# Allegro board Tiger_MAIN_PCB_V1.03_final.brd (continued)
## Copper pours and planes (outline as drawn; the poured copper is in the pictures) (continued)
+V3P3A_DSW on TOP (solid shape): 143.64,93.38 143.64,88.98 143.41,88.76 142.41,88.76 142.17,89 142.17,93.23 142.4,93.45 143.57,93.45
+V3P3A_DSW on TOP (solid shape): outline of 113 points within 7.45,60.28 19.2,69.48
+V3P3A_DSW on BOTTOM (solid shape): 37.52,56.22 37.52,53.65 37.32,53.46 36.44,53.46 35.46,54.44 35.46,55.96 35.85,56.36 37.38,56.36
+V3P3A_DSW on LAY6 (solid shape): outline of 455 points within 9.48,48.32 37.95,63.17
+V3P3A_RTC on BOTTOM (solid shape): 197.68,61.61 197.76,61.53 197.82,61.53 197.93,61.42 197.93,61.19 197.91,61.15 197.88,61.14 197.55,60.92 197.62,60.53 197.64,60.49 197.64,60.44 197.64,59.85 197.64,59.8 197.62,59.76 197.52,59.51 197.65,59.2 197.52,58.88 197.65,58.56 197.62,58.49 197.52,58.18 197.72,57.92 197.74,57.91 197.77,57.87 197.77,55.43 196.97,54.63 196.73,54.63 195.99,53.9 195.99,53.65 195.05,52.71 194.49,52.71 194.28,52.5 194.28,51.52 193.74,50.99 193.74,49.84 193.46,49.56 193.19,49.56 192.97,49.78 192.97,53.14 194.42,54.58 195.64,54.58 197.09,56.04 197.09,56.06 197.12,56.11 197.13,56.11 197.29,56.41 197.13,56.7 197.12,56.71 197.09,56.75 197.09,57.26 197.13,57.29 197.31,57.55 197.22,57.86 197.19,57.93 197.32,58.24 197.19,58.56 197.32,58.88 197.19,59.2 197.32,59.51 197.19,59.83 197.32,60.15 197.19,60.47 197.32,60.78 197.19,61.1 197.22,61.17 197.3,61.32 197.31,61.49 197.33,61.58 197.4,61.62 197.66,61.62
+V3P3A_SIP on BOTTOM (solid shape): 175.72,44.14 175.72,43.7 177.23,42.19 180.37,42.19 180.57,42.39 180.57,43.46 180.67,43.56 181.61,43.56 181.77,43.4 181.77,41.79 181.53,41.55 176.76,41.55 175.06,43.25 175.06,44.13 175.14,44.2 175.66,44.2
+V3P3A_SIP on BOTTOM (solid shape): 169.59,63.27 169.59,62.06 169.59,62.02 169.59,61.98 169.59,61.08 169.56,61.01 169.5,60.98 169.39,60.95 169.3,60.9 169.06,60.99 168.82,60.9 168.59,60.97 168.36,60.88 168.27,60.77 168.23,60.62 168.22,60.58 166.83,60.58 166.67,60.42 166.67,60.28 166.66,60.19 166.67,60.11 166.67,59.8 166.63,59.77 166.63,59.43 166.87,59.19 167.21,59.19 167.33,59.08 167.33,57.59 167.29,57.58 166.91,57.25 167.01,56.76 167.01,56.76 167.02,56.72 167.01,56.69 167.01,56.68 166.9,56.47 166.9,56.24 167.04,56 167.3,55.86 167.33,55.86 167.33,54.83 168.78,53.39 168.78,51.58 168.6,51.41 168.28,51.41 168.05,51.63 168.05,53.16 166.27,54.94 166.27,56.16 166.44,56.34 166.46,56.59 166.35,56.78 166.14,56.87 166.12,56.88 165.85,57.15 165.85,57.8 165.89,57.87 165.96,57.9 166.36,58.28 165.96,58.65 165.89,58.68 165.85,58.76 165.85,61.58 166.38,62.1 168.03,62.1 168.04,62.1 168.33,62.16 168.49,62.42 168.48,62.56 168.42,62.69 168.42,63.22 168.55,63.34 169.52,63.34
+V3P3A_SIP on BOTTOM (solid shape): 199.45,62.85 199.48,62.77 199.27,62.39 199.4,62.05 199.53,61.92 199.53,61.16 199.5,61.15 199.26,60.84 199.39,60.48 199.42,60.42 199.41,60.35 199.35,60.12 199.45,59.9 199.48,59.83 199.35,59.51 199.48,59.2 199.35,58.88 199.48,58.56 199.45,58.49 199.35,58.24 199.45,57.99 199.48,57.92 199.45,57.85 199.35,57.6 199.46,57.31 199.44,57.28 198.88,56.71 198.88,54.05 198.81,53.86 198.88,53.66 198.88,53.49 199.08,53.29 199.08,52.12 198.66,51.69 198.09,51.69 198.04,51.75 198.04,52.19 198.37,52.53 198.37,54.56 198.55,54.73 198.55,56.89 198.88,57.22 198.91,57.26 199.14,57.52 199.04,57.85 199.01,57.92 199.04,57.99 199.15,58.24 199.04,58.49 199.02,58.56 199.15,58.88 199.02,59.2 199.15,59.51 199.02,59.83 199.15,60.15 199.02,60.47 199.15,60.78 199.02,61.1 199.04,61.17 199.14,61.5 198.91,61.75 198.89,61.76 198.87,61.79 198.87,61.87 198.57,62.18 198.56,62.2 198.56,62.24 198.56,62.52 198.34,62.71 198.33,62.72 198.29,62.77 198.29,62.82 198.33,62.87 198.34,62.87 198.54,63.03 198.58,63.27 198.58,63.3 198.6,63.32 198.69,63.41 198.89,63.41
+V3P3A_SIP on BOTTOM (solid shape): outline of 1072 points within 175.25,46.69 196.12,61.75
+V3P3A_SIP on LAY4 (solid shape): outline of 450 points within 183.32,55.17 196.77,61.87
+V3P3A_SIP on LAY6 (solid shape): outline of 717 points within 193.86,61.35 199.79,68.02
+V5_AVDD on BOTTOM (solid shape): 9.34,14.93 9.34,14.18 9.24,14.08 8.75,14.08 8.21,13.54 8.21,9.58 8.13,9.5 6.64,9.5 6.54,9.6 6.54,14.05 7.5,15.02 9.25,15.02
+V5_PVDD on BOTTOM (solid shape): 12.95,26.96 14.13,26.96 14.27,26.83 14.27,25.84 14.17,25.73 12.46,25.73 11.84,26.36 11.23,26.36 11.11,26.48 11.11,27.33 11.19,27.42 12.49,27.42
+V5A on TOP (solid shape): 62.78,14.15 62.78,10.61 62.45,10.28 61.14,10.28 60.79,10.63 60.79,14.14 61.02,14.37 62.56,14.37
+V5A on TOP (solid shape): 41.9,19.76 41.9,17.87 41.89,17.86 41.89,16.05 41.89,15.82 41.76,15.7 40.6,15.7 40.5,15.8 40.5,17.38 40.22,17.65 39.76,17.65 39.42,18 39.42,19.73 39.57,19.88 41.77,19.88
+V5A on TOP (solid shape): outline of 326 points within 17.9,64.26 32.52,76.37
+V5A on BOTTOM (solid shape): 152.32,45.11 152.32,43.9 152.02,43.61 151.59,43.61 151.06,44.14 151.06,45.09 151.21,45.25 152.18,45.25
+V5A on BOTTOM (solid shape): 235.84,91 235.84,90.28 235.79,90.22 235.01,90.22 234.71,90.52 234.71,91.37 234.77,91.43 235.41,91.43
+V5A on BOTTOM (solid shape): 54.89,88.13 54.89,83.61 53.56,82.28 30.63,82.28 28.54,84.37 22.97,84.37 22.69,84.65 22.69,87.54 23,87.84 25.85,87.84 26.94,88.93 28.54,88.93 29.44,88.03 29.44,86.44 32.03,83.85 52.7,83.85 53.35,84.5 53.35,85.98 52.84,86.49 49.71,86.49 49.47,86.73 49.47,89.14 50.32,90 53.03,90
+V5A on BOTTOM (solid shape): outline of 551 points within 24.94,10.55 62.08,42.95
+V5A on BOTTOM (solid shape): outline of 996 points within 36.1,41.94 124.71,57.06
+V5A on LAY3 (solid shape): outline of 811 points within 25.55,40.69 37.34,72.46
+V5A on LAY6 (solid shape): outline of 434 points within 19.69,69.99 32.03,88.71
+V5S on TOP (solid shape): 34,80.4 34,77.38 33.51,76.88 29.08,76.88 29.02,76.93 29.02,80.72 29.24,80.93 33.47,80.93
+V5S on BOTTOM (solid shape): 6.18,14.66 6.18,9.52 5.91,9.25 4.64,9.25 4.18,9.71 4.18,15.04 4.32,15.17 5.67,15.17
+V5S on BOTTOM (solid shape): 13.53,31.67 13.53,30.69 12.65,29.81 12.65,28.11 12.54,27.99 11,27.99 10.89,28.11 10.89,31.79 11.59,32.49 12.71,32.49
+V5S on BOTTOM (solid shape): outline of 1029 points within 23.22,44.81 123.49,81.36
+V5S on LAY3 (solid shape): outline of 2288 points within 11.68,29.27 32.67,83.49
+V5S_HDD on TOP (solid shape): 102.5,56.35 102.5,55.56 102.46,55.53 99.93,55.53 99.88,55.48 99.88,55.23 99.93,55.19 102.45,55.19 102.51,55.13 102.51,54.32 102.44,54.25 98.03,54.25 97.82,54.47 97.82,56.18 98.06,56.43 102.42,56.43
+V5S_HDD on BOTTOM (solid shape): 98.24,61.96 98.34,61.92 98.45,61.91 98.47,61.91 98.58,61.8 98.58,61.46 98.56,61.44 98.36,61.11 98.56,60.77 98.58,60.76 98.58,56.04 99.02,55.61 100.69,55.61 100.8,55.5 100.8,54.55 100.75,54.5 97.27,54.5 97.03,54.75 97.03,61.77 97.22,61.96
+VCCCORE on TOP (solid shape): outline of 157 points within 191.45,81.79 204.41,101.96
+VCCCORE on TOP (solid shape): outline of 580 points within 204.03,60.49 209.89,63.44
+VCCCORE on TOP (solid shape): outline of 675 points within 204.16,71.34 211.31,73.93
+VCCCORE on BOTTOM (solid shape): outline of 3573 points within 186.63,60.61 214.81,95.53
+VCCCORE on LAY3 (solid shape): outline of 791 points within 203.55,62.1 211.17,72.51
+VCCCORE on LAY4 (solid shape): outline of 4930 points within 186.94,62.05 215.88,93.84
+VCCGT on TOP (solid shape): outline of 1039 points within 210.09,60.56 220.46,63.44
+VCCGT on TOP (solid shape): outline of 1526 points within 215.23,84.94 243.15,102.4
+VCCGT on TOP (solid shape): outline of 3320 points within 211.51,63.83 238.66,73.35
+VCCGT on BOTTOM (solid shape): 220.79,83.49 220.9,83.51 220.96,83.42 220.96,83.21 220.89,83.21 220.89,82.46 221.22,82.46 221.24,82.43 221.27,82.32 221.17,82.26 220.89,82.26 220.89,81.78 220.67,81.56 220.67,81.25 220.49,81.08 220.47,81.08 220.41,81.08 220.35,81.07 220.26,81.09 220.22,81.17 220.22,81.64 220.26,81.72 220.35,81.74 220.71,81.91 220.64,82.3 220.6,82.38 220.75,82.71 220.6,83.03 220.64,83.11 220.73,83.25 220.75,83.41 220.74,83.44
+VCCGT on BOTTOM (solid shape): outline of 5992 points within 210.4,51.98 240.15,102.24
+VCCGT on LAY3 (solid shape): outline of 3155 points within 210.16,62.09 238.71,80.79
+VCCGT on LAY4 (solid shape): outline of 5606 points within 210.05,62.05 238.68,93.52
+VCCPAZIO on BOTTOM (solid shape): 197.78,62.48 197.85,62.45 197.88,62.38 198.03,62.08 198.37,62.05 198.4,62.06 198.6,61.86 198.63,61.78 198.43,61.45 198.53,61.17 198.56,61.1 198.43,60.78 198.56,60.47 198.43,60.15 198.56,59.83 198.43,59.51 198.56,59.2 198.43,58.88 198.56,58.56 198.53,58.49 198.43,58.24 198.54,57.99 198.57,57.92 198.54,57.85 198.44,57.67 198.46,57.46 198.47,57.42 198.31,57.26 198.31,54.78 198.1,54.57 198.1,52.49 197.35,51.74 196.57,51.74 196.44,51.87 196.44,52.76 196.89,53.2 196.89,53.22 197.41,53.74 197.41,54.81 197.97,55.38 197.97,57.86 198,57.91 198.02,57.92 198.22,58.17 198.13,58.49 198.1,58.56 198.23,58.88 198.1,59.2 198.23,59.51 198.13,59.76 198.11,59.8 198.1,59.84 198.1,60.46 198.11,60.5 198.13,60.53 198.23,60.78 198.13,61.03 198.13,61.17 198.19,61.57 197.84,61.77 197.81,61.77 197.33,62.25 197.33,62.48
+VCCPDSW_3P3 on BOTTOM (solid shape): outline of 396 points within 180.59,44 196.79,62.53
+VCCPDSW_3P3 on LAY3 (solid shape): 196.56,65.21 196.56,64.47 196.51,64.39 196.42,64.38 196.16,64.39 195.96,64.21 195.97,64.17 195.95,64.06 195.97,63.95 195.95,63.91 196.15,63.72 196.42,63.72 196.51,63.72 196.56,63.63 196.56,62.31 196.45,62.2 195.36,62.2 195.31,62.25 195.31,62.28 195.29,62.51 195.14,62.69 195.12,62.7 195.09,62.74 195.09,62.85 195.12,62.89 195.18,62.93 195.22,62.96 195.29,62.99 195.36,62.96 195.97,63.21 195.36,63.46 195.29,63.43 195.22,63.46 195.18,63.5 195.12,63.53 195.09,63.58 194.93,63.74 194.93,64.38 195.12,64.57 195.18,64.6 195.22,64.64 195.29,64.67 195.36,64.64 195.97,64.89 195.36,65.14 195.29,65.11 195.22,65.14 195.18,65.17 195.12,65.21 195.09,65.26 195.09,65.35 195.12,65.38 196.38,65.38
+VCCSA on TOP (solid shape): 177.65,93.8 177.65,89.01 177.49,88.84 176.47,88.84 175.98,89.34 172.79,89.34 172.78,89.33 172.2,89.33 171.7,88.83 169.04,88.83 168.55,89.33 168.55,93.28 169.52,94.25 177.2,94.25
+VCCSA on TOP (solid shape): outline of 462 points within 199.62,71.34 203.95,73.95
+VCCSA on BOTTOM (solid shape): outline of 1170 points within 171.13,62.76 203.26,93.34
+VCCSA on LAY3 (solid shape): 201.15,72.58 201.24,72.53 201.24,72.43 201.53,71.95 201.82,72.43 201.83,72.53 201.91,72.58 202.96,72.58 203.07,72.46 203.07,72.43 203.07,72.42 203.05,72.16 203.23,71.97 203.24,71.97 203.26,71.94 203.26,70.1 203.21,70.01 203.12,70 202.68,69.69 203.12,69.39 203.21,69.38 203.26,69.29 203.26,64.24 203.25,64.21 203.22,64.19 202.95,63.87 203.22,63.55 203.25,63.53 203.26,63.5 203.26,63.21 202.87,62.81 202.39,62.81 202.3,62.86 202.29,62.95 201.99,63.4 201.69,62.95 201.68,62.86 201.59,62.81 200.09,62.81 199.93,62.97 199.93,63.19 200.42,63.67 200.42,69.27 200.45,69.35 200.53,69.37 200.92,69.69 200.53,70.02 200.45,70.04 200.42,70.12 200.42,72.44 200.55,72.58
+VCCSA on LAY4 (solid shape): outline of 2014 points within 171.4,62.76 203.26,91.74
+VDDQ_MEM on TOP (solid shape): outline of 660 points within 202.63,23.3 249.6,52.36
+VDDQ_MEM on BOTTOM (solid shape): outline of 3786 points within 199.03,35.59 219.75,62.2
+VDDQ_MEM on BOTTOM (solid shape): outline of 6340 points within 181.8,11.59 237.98,24.91
+VDDQ_VTT on TOP (solid shape): 173.73,11.93 178.29,11.93 178.48,11.74 178.48,11.01 178.28,10.8 177.55,10.8 177.48,10.73 172.93,10.73 172.7,10.96 172.7,12.23 172.88,12.4 173.26,12.4
+VDDQ_VTT on BOTTOM (solid shape): 234.85,40.52 234.85,37.05 234.69,36.89 233,36.89 232.83,37.05 232.83,39.68 231.91,40.61 231.91,41.97 232.14,42.2 233.18,42.2
AGND on BOTTOM (solid shape): 7.3,19.75 7.3,18.87 6.99,18.56 5.2,18.56 4.86,18.91 4.86,19.78 5.07,20 7.04,20
AGND on BOTTOM (solid shape): 10.42,14.25 10.42,11.76 9.9,11.24 8.63,11.24 8.49,11.38 8.49,13.5 8.74,13.75 9.21,13.75 9.79,14.33 10.33,14.33
AGND on LAY2 (solid shape): outline of 1201 points within 6.34,7.04 60.64,32.05
AGND on LAY7 (solid shape): outline of 1403 points within 4.83,8.77 38.57,30.31
GND on TOP (solid shape): 6.77,65.92 6.77,61.16 6.35,60.73 3.4,60.73 2.51,61.63 2.51,66.01 2.91,66.42 6.28,66.42
GND on TOP (solid shape): 21.21,83.68 21.21,81.17 20.81,80.77 16.99,80.77 16.69,81.06 16.69,83.65 17.07,84.03 20.86,84.03
GND on TOP (solid shape): 40.12,17.25 40.12,15.56 39.98,15.43 38.85,15.43 38.67,15.61 38.67,17.19 38.85,17.37 39.99,17.37
GND on TOP (solid shape): 64.8,14.06 64.8,10.41 64.55,10.16 63.34,10.16 63.14,10.35 63.14,14.07 63.33,14.25 64.61,14.25
GND on TOP (solid shape): 67.1,12.94 67.1,11.17 66.98,11.05 65.52,11.05 65.34,11.23 65.34,12.93 65.58,13.17 66.87,13.17
GND on TOP (solid shape): 140.25,70.56 140.25,67.46 139.9,67.1 136.42,67.1 134.64,68.88 134.64,70.49 135.04,70.9 139.91,70.9
GND on TOP (solid shape): 150.89,53.15 150.89,51.9 150.74,51.75 148.37,51.75 148.18,51.94 148.18,52.42 149.07,53.31 150.73,53.31
GND on TOP (solid shape): 171.46,83.47 171.46,82.93 171.39,82.86 170.08,82.86 170,82.93 170,83.47 170.08,83.54 171.39,83.54
GND on TOP (solid shape): 226.26,90.25 226.26,87.79 226.02,87.55 224.76,87.55 224.68,87.63 224.68,90.44 224.74,90.51 226.01,90.51
GND on TOP (solid shape): 49.48,16.46 49.48,14.44 49.33,14.29 46.15,14.29 45.91,14.54 45.91,16.03 46.49,16.61 49.34,16.61
GND on TOP (solid shape): 64.24,18.3 65.74,18.3 65.86,18.18 65.86,17.52 65.74,17.4 63.19,17.4 63.08,17.51 63.08,18.37 63.17,18.46 64.08,18.46
GND on TOP (solid shape): 79.87,22.65 79.87,17.55 79.72,17.41 77.45,17.41 77.07,17.79 77.07,22.5 77.41,22.84 79.68,22.84
GND on TOP (solid shape): 105.69,22.52 105.69,19.8 105.33,19.44 102.95,19.44 102.6,19.79 102.6,21.81 103.67,22.87 105.35,22.87
GND on TOP (solid shape): 119.28,10.32 119.28,7.15 119.14,7.01 106.37,7.01 106.18,7.2 106.18,7.87 106.29,7.98 107.27,7.98 110.48,11.2 118.41,11.2
GND on TOP (solid shape): 129.82,10.65 129.82,9.36 129.35,8.89 129.35,8.05 129.22,7.91 128.57,7.91 127.98,8.49 127.98,10.41 128.44,10.87 129.61,10.87
GND on TOP (solid shape): 148.14,59.42 148.14,58.75 147.9,58.5 147.01,58.5 146.61,58.11 146.03,58.11 145.97,58.17 145.97,59.47 146.07,59.57 147.99,59.57
GND on TOP (solid shape): 168.33,24.18 169.08,24.18 169.33,23.92 169.33,23.08 169.16,22.91 166.97,22.91 166.55,23.33 166.55,24.36 166.71,24.51 167.99,24.51
GND on TOP (solid shape): 185.91,92.16 185.91,88.95 185.62,88.65 178.7,88.65 178.36,89 178.36,92.29 178.56,92.49 185.58,92.49
GND on TOP (solid shape): 240.77,73.17 240.77,67.23 240.56,67.01 238.99,67.01 238.94,67.06 238.94,73.17 239.1,73.33 240.62,73.33
GND on TOP (solid shape): 25.08,95.59 25.08,93.74 24.85,93.51 24.74,93.4 20.74,93.4 20.54,93.61 20.54,95.45 21.04,95.95 24.72,95.95
GND on TOP (solid shape): 28.67,82.04 28.67,81.03 28.09,80.45 27.49,80.45 27.13,80.09 25.44,80.09 25.27,80.27 25.27,81.75 25.68,82.16 28.54,82.16
GND on TOP (solid shape): 37.91,80.58 37.91,76.06 37.64,75.78 34.47,75.78 34.24,76.01 34.24,80.4 34.65,80.81 37.69,80.81
GND on TOP (solid shape): 48.75,10.87 48.75,9.49 48.43,9.16 46.26,9.16 45.95,9.47 45.95,10.8 46.25,11.1 47.34,11.1 48.52,11.1
GND on TOP (solid shape): 51.31,12.73 51.31,11.32 51.49,11.14 51.49,10.23 51.27,10.01 49.9,10.01 49.65,10.25 49.65,12.81 49.85,13.01 51.03,13.01
GND on TOP (solid shape): 111.96,28.03 111.96,25.46 113.13,24.3 113.13,20.85 112.74,20.47 109.23,20.47 107.97,21.73 107.97,27.09 109.16,28.28 111.71,28.28
GND on TOP (solid shape): 176.8,103.48 176.8,102.34 176.65,102.19 171.91,102.19 171.67,102.43 171.67,103.49 171.89,103.7 176.57,103.7
GND on TOP (solid shape): 17.68,104.01 17.68,93.38 17.31,93.01 14.07,93.01 13.74,93.34 13.74,94.71 14,94.96 15.87,94.96 16.07,95.16 16.07,103.84 16.46,104.23 17.47,104.23
GND on TOP (solid shape): 186.08,85.37 186.08,83.94 185.87,83.72 179.32,83.72 179.15,83.9 179.15,84.57 179.68,85.11 179.68,85.4 179.7,85.42 186.04,85.42
GND on TOP (solid shape): 248.77,57.5 248.77,53.48 247.93,52.64 237.77,52.64 237.67,52.74 237.67,53.65 237.69,53.67 237.69,54.08 239.29,55.69 239.29,57.48 239.67,57.86 248.42,57.86
GND on TOP (solid shape): 1.87,104.07 1.87,95.56 2.25,95.18 3.72,95.18 4.01,94.89 4.01,93.42 3.54,92.95 0.61,92.95 0.27,93.29 0.27,104.23 0.5,104.46 1.48,104.46
GND on TOP (solid shape): 76.17,25.51 76.17,24.43 76.53,24.06 76.53,22.54 76.37,22.38 73.79,22.38 73.44,22.73 73.44,25.45 73.8,25.81 75.87,25.81
GND on TOP (solid shape): 203.1,87.24 203.1,82.73 203.05,82.68 201.5,82.68 201.41,82.77 201.41,85.07 201.49,85.14 201.69,85.14 201.84,85.3 201.84,87.29 201.98,87.43 202.91,87.43
GND on TOP (solid shape): 236.74,72 236.74,71.61 236.64,71.5 234.49,71.5 234.15,71.16 229.7,71.16 229.61,71.26 229.61,71.67 229.77,71.84 230.5,71.84 230.8,72.14 236.6,72.14
GND on TOP (solid shape): 23.44,56.97 24.12,56.97 24.76,56.33 25.05,56.33 25.34,56.05 25.34,54.33 25.01,54.01 19.84,54.01 19.47,54.38 19.47,58.16 19.7,58.39 22.01,58.39
GND on TOP (solid shape): 172.92,10.45 177.53,10.45 177.67,10.59 178.19,10.59 178.48,10.3 178.48,9.34 178.17,9.04 176.04,9.04 175.63,9.44 172.69,9.44 172.41,9.72 172.41,10.51 172.53,10.64 172.73,10.64
GND on TOP (solid shape): 17.02,80.37 17.02,78.43 16.93,78.34 16.03,78.34 15.97,78.41 15.97,78.56 15.96,78.57 15.96,78.93 15.84,79.04 15.58,79.04 14.6,80.02 14.6,80.54 14.79,80.73 16.67,80.73
GND on TOP (solid shape): 169.07,58.59 169.07,58.02 169.32,57.77 169.32,56.23 169.14,56.05 166.98,56.05 166.85,56.19 166.85,57.86 167.01,58.02 168.17,58.02 168.33,58.19 168.33,58.59 168.41,58.67 168.99,58.67
GND on TOP (solid shape): 36.1,74.23 36.1,67.06 35.5,66.46 35.5,64.34 35.24,64.08 30.12,64.08 29.94,64.26 29.94,67.67 32.83,70.57 32.83,74.79 32.92,74.87 35.45,74.87
GND on TOP (solid shape): 11.65,84.11 11.65,83.36 11.49,83.19 10.78,83.19 10.49,82.9 10.49,79 10.05,78.55 4.75,78.55 4.43,78.88 4.43,83.22 5.4,84.2 11.56,84.2
GND on TOP (solid shape): 165.96,52.29 165.96,49.68 165.57,49.29 164.36,49.29 164.35,49.33 164.23,49.49 164.05,49.57 164.03,49.57 163.97,49.64 163.97,52.2 164.24,52.47 165.78,52.47
GND on TOP (solid shape): 231.27,66.41 233.68,66.41 234.05,66.78 234.33,66.78 234.7,66.41 237.35,66.41 237.52,66.24 237.52,65.51 237.38,65.38 230.26,65.38 229.98,65.65 229.98,66.67 230.12,66.81 230.5,66.81 230.51,66.82 230.86,66.82
GND on TOP (solid shape): 131.15,73.04 131.35,72.99 131.55,73.04 131.76,73.04 131.95,72.99 132.15,73.04 134.36,73.04 134.52,72.88 134.52,71.01 134.39,70.88 128.85,70.88 128.39,71.34 128.39,72.55 128.88,73.04
GND on TOP (solid shape): 166.45,86.19 166.45,84.47 166.39,84.26 166.45,84.05 166.45,82.83 162.84,79.22 157.79,79.22 157.46,79.55 157.46,82.18 158.01,82.72 161.49,82.72 162.1,83.33 162.1,83.68 162.59,84.17 162.93,84.17 163.35,84.59 163.35,85.47 163.33,85.49 163.33,86.5 163.42,86.58 166.06,86.58
GND on TOP (solid shape): 217.21,103.98 217.21,101.18 216.87,100.83 216.78,100.89 216.76,100.89 216.58,100.92 216.41,100.89 216.39,100.89 216.32,100.84 216.27,100.81 215.6,100.81 215.3,101.11 215.3,103.01 215.08,103.22 213.77,103.22 213.58,103.03 212.83,103.03 212.7,103.16 212.7,104.01 212.92,104.22 216.97,104.22
GND on TOP (solid shape): 15.14,60 19.02,60 19.17,59.85 19.17,58.41 19.1,58.31 18.99,58.34 18.53,58.42 18.35,58 18.33,57.91 18.25,57.87 12.54,57.87 12.41,58 12.41,60.18 12.62,60.38 14.76,60.38
GND on TOP (solid shape): 171.49,62.95 171.49,60.99 171.48,60.95 171.44,60.94 171.08,60.69 171.19,60.27 171.23,60.2 171.2,60.12 171.17,60.1 168.81,60.1 168.56,59.86 168.56,59.33 168.49,59.25 168.22,59.25 168.17,59.3 168.17,60.84 168.41,61.08 170.15,61.08 170.29,61.22 170.29,62.85 170.55,63.11 171.33,63.11
GND on TOP (solid shape): 34.26,62.3 34.26,59.19 34.02,58.95 29.44,58.95 29.2,59.19 29.2,60.05 29.3,60.16 29.66,60.16 29.7,60.2 29.73,60.2 29.73,60.22 29.89,60.38 29.89,61.01 30.14,61.26 30.15,61.26 30.24,61.34 30.32,61.43 30.33,61.46 30.34,61.48 30.36,61.6 30.34,61.72 30.33,61.75 30.32,61.77 30.24,61.87 30.15,61.94 30.12,61.96 30.04,61.98 29.99,61.98 29.92,62.01 29.89,62.08 29.89,62.64 30.33,63.09 33.47,63.09
GND on TOP (solid shape): 174,49.75 174,49.07 173.2,48.27 171.77,48.27 171.72,48.32 171.72,48.74 171.73,48.74 171.73,49.19 172.92,49.19 172.92,49.14 172.94,49.09 172.96,49.04 172.99,48.99 173.02,48.95 173.07,48.91 173.11,48.88 173.16,48.85 173.21,48.84 173.27,48.83 173.32,48.83 173.38,48.84 173.43,48.85 173.48,48.88 173.53,48.91 173.57,48.95 173.6,48.99 173.63,49.04 173.66,49.09 173.67,49.14 173.68,49.19 173.67,49.25 173.66,49.3 173.65,49.36 173.62,49.41 173.59,49.45 173.55,49.49 173.51,49.52 173.46,49.55 173.41,49.57 173.35,49.58 173.3,49.59 173.24,49.58 173.19,49.57 173.14,49.55 173.09,49.52 173.04,49.49 173.01,49.45 172.97,49.41 172.95,49.36 172.93,49.3 172.92,49.25 172.92,49.19 171.73,49.19 171.73,49.76 171.9,49.93 173.82,49.93
GND on TOP (solid shape): 159.51,47.99 159.51,46.66 159.5,46.66 157.96,46.66 156.63,45.33 154.5,45.33 154.04,45.79 154.04,46.03 154.1,46.12 154.2,46.12 154.78,46.44 154.2,46.76 154.1,46.76 154.04,46.85 154.04,47.96 154.16,48.08 159.43,48.08
GND on TOP (solid shape): 3.89,92.15 3.89,88.97 3.88,88.96 3.88,87.49 3.84,87.48 2.84,86.25 3.84,85.03 3.88,85.02 3.88,68.41 2.05,66.58 2.05,61.32 6.53,56.84 16.71,56.84 19.96,53.59 19.96,43.87 4.19,28.11 4.19,20.47 2.05,18.33 2.05,10.12 3.21,8.96 14.93,8.96 16.54,7.35 52.58,7.35 53.49,8.25 54.4,8.25 54.69,7.96 54.69,7.25 54.45,7.01 0.41,7.01 0.41,92.03 0.86,92.48 3.56,92.48
GND on TOP (solid shape): 187.79,96.67 187.79,93.3 187.52,93.04 180.05,93.04 178.55,94.53 170.38,94.53 170.08,94.83 170.08,96.12 170.81,96.85 174.52,96.85 175.27,96.1 182.15,96.1 182.24,96.05 182.25,95.95 182.85,95.26 182.95,96.17 182.9,96.25 182.93,96.33 183.59,96.99 187.46,96.99
GND on TOP (solid shape): 221.25,94.81 221.25,92.68 220.76,92.18 215.31,92.18 214.78,91.65 214.78,91.45 214.78,91.44 214.78,84.59 214.58,84.38 210.13,84.38 209.83,84.68 209.83,90.89 210.18,91.23 210.18,93.71 215.83,93.71 215.84,93.65 215.85,93.58 215.87,93.52 215.9,93.47 215.93,93.41 215.97,93.36 216.02,93.32 216.07,93.28 216.12,93.25 216.18,93.23 216.24,93.21 216.31,93.21 216.37,93.21 216.43,93.21 216.49,93.23 216.55,93.25 216.61,93.28 216.66,93.32 216.7,93.36 216.74,93.41 216.78,93.47 216.81,93.52 216.82,93.58 216.84,93.65 216.84,93.71 216.84,93.77 216.82,93.83 216.81,93.89 216.78,93.95 216.74,94.01 216.7,94.05 216.66,94.1 216.61,94.13 216.55,94.16 216.49,94.19 216.43,94.2 216.37,94.21 216.31,94.21 216.24,94.2 216.18,94.19 216.12,94.16 216.07,94.13 216.02,94.1 215.97,94.05 215.93,94.01 215.9,93.95 215.87,93.89 215.85,93.83 215.84,93.77 215.83,93.71 210.18,93.71 210.18,94.69 210.58,95.09 220.97,95.09
GND on TOP (solid shape): 207.16,97.36 207.23,97.33 207.26,97.25 207.76,96.71 208.26,97.25 208.29,97.33 208.36,97.36 208.5,97.36 208.99,96.87 208.99,96.33 209.58,95.75 209.58,88.12 209.09,87.63 205.35,87.63 204.55,88.43 204.55,89.11 204.74,89.3 204.74,92.61 204.39,92.95 204.39,97.2 204.46,97.26 204.5,97.23 204.84,97.11 205.13,97.33 205.14,97.36
GND on TOP (solid shape): outline of 102 points within 60.92,7.01 102.85,12.96
GND on TOP (solid shape): outline of 107 points within 159.8,70.95 166.67,76.86
GND on TOP (solid shape): outline of 211 points within 243.11,87.09 249.29,102.52
GND on TOP (solid shape): outline of 698 points within 43.06,7.01 252.89,105.19
GND on BOTTOM (solid shape): 4.33,19.58 4.33,18.89 4.08,18.64 2.09,18.64 1.88,18.85 1.88,19.7 2.04,19.87 4.04,19.87
GND on BOTTOM (solid shape): 10.24,31.66 10.24,29.07 10.04,28.87 8.67,28.87 8.34,29.2 8.34,31.5 8.63,31.79 10.11,31.79
GND on BOTTOM (solid shape): 10.8,92.5 10.8,88.1 10.55,87.84 8.39,87.84 8.18,88.04 8.18,92.44 8.49,92.74 10.56,92.74
GND on BOTTOM (solid shape): 76.62,36.09 76.62,34.96 76.51,34.84 75.2,34.84 75.1,34.95 75.1,36.09 75.23,36.22 76.5,36.22
GND on BOTTOM (solid shape): 109.87,97.7 109.87,96.22 109.75,96.1 107.89,96.1 107.76,96.22 107.76,97.68 107.89,97.81 109.76,97.81
GND on BOTTOM (solid shape): 116.06,90.98 116.06,86.23 115.82,85.99 113.95,85.99 113.51,86.43 113.51,90.72 113.86,91.08 115.96,91.08
GND on BOTTOM (solid shape): 119.96,50.21 119.96,48.62 119.79,48.46 117.18,48.46 117.05,48.59 117.05,50.19 117.28,50.41 119.75,50.41
GND on BOTTOM (solid shape): 143.6,28.42 143.6,24.9 143.48,24.77 140.7,24.77 140.48,24.99 140.48,28.19 140.78,28.49 143.53,28.49
GND on BOTTOM (solid shape): 152.27,48.08 152.27,45.77 152.02,45.53 150.65,45.53 150.44,45.74 150.44,48.19 150.63,48.38 151.96,48.38
GND on BOTTOM (solid shape): 182.07,47.51 182.07,45.33 181.93,45.19 180.47,45.19 180.2,45.46 180.2,47.69 180.37,47.86 181.73,47.86
GND on BOTTOM (solid shape): 189.95,92.07 189.95,88.53 189.72,88.3 187.9,88.3 187.72,88.48 187.72,91.22 188.79,92.29 189.73,92.29
GND on BOTTOM (solid shape): 209.54,68.33 209.54,65.46 209.49,65.41 208.63,65.41 208.53,65.51 208.53,68.31 208.68,68.46 209.42,68.46
GND on BOTTOM (solid shape): 221.85,66 221.85,65.12 221.81,65.08 220.49,65.08 220.43,65.15 220.43,66.04 220.5,66.11 221.73,66.11
GND on BOTTOM (solid shape): 233.67,34.41 233.67,32.55 233.53,32.41 230.75,32.41 230.26,32.9 230.26,34.3 230.64,34.68 233.41,34.68
GND on BOTTOM (solid shape): 52.89,85.83 52.89,84.73 52.35,84.2 50.17,84.2 49.89,84.48 49.89,85.93 50.12,86.15 52.56,86.15
GND on BOTTOM (solid shape): 141.55,39.14 141.55,37.46 141.19,37.11 140.09,37.11 139.73,37.46 139.73,39.61 139.87,39.75 140.94,39.75
GND on BOTTOM (solid shape): 174.91,27.88 174.91,26.72 174.72,26.53 171.62,26.53 171.48,26.67 171.48,28.03 171.61,28.15 174.64,28.15
GND on BOTTOM (solid shape): 114.08,50.62 114.08,49.4 113.85,49.17 111,49.17 110.84,49.34 110.84,50.68 111.05,50.9 113.8,50.9
GND on BOTTOM (solid shape): 139.46,17.7 139.46,15.58 139.41,15.53 134.88,15.53 134.65,15.76 134.65,17.59 134.92,17.85 139.31,17.85
GND on BOTTOM (solid shape): 187.9,24.45 187.9,23.09 187.54,22.72 182.32,22.72 181.99,23.05 181.99,24.19 182.51,24.71 187.64,24.71
GND on BOTTOM (solid shape): 206.49,68.58 206.49,66.14 206.42,66.06 205.36,66.06 205.33,66.1 205.33,68.56 205.42,68.65 206.42,68.65
GND on BOTTOM (solid shape): 28.83,83.7 28.83,81.66 28.66,81.48 28.01,81.48 26.78,80.25 25.02,80.25 24.35,80.92 24.35,83.71 24.74,84.11 28.43,84.11
GND on BOTTOM (solid shape): 96.72,59.75 96.72,54.79 96.53,54.6 92.76,54.6 92.5,54.86 92.5,59.65 92.75,59.9 94.37,59.9 94.39,59.92 96.54,59.92
GND on BOTTOM (solid shape): 158.99,59.11 158.99,57.34 158.69,57.03 157.61,57.03 157.53,57.11 157.53,58.82 157.54,58.82 157.54,59.47 157.64,59.57 158.53,59.57
GND on BOTTOM (solid shape): 123.03,92.49 123.03,86.29 123.02,86.28 120.68,86.28 120.53,86.43 120.53,89.72 121.43,90.62 121.43,91.58 121.33,91.68 121.33,92.24 121.62,92.53 122.99,92.53
GND on BOTTOM (solid shape): 125.29,88.88 125.29,85.59 125.3,85.58 125.3,81.99 125.07,81.76 124,81.76 123.59,82.16 123.59,85.54 123.64,85.59 123.64,88.96 123.73,89.05 125.13,89.05
GND on BOTTOM (solid shape): 130.77,29.42 130.77,29.24 130.78,29.24 130.78,28.46 130.53,28.22 127.68,28.22 127.55,28.35 127.55,29.46 127.72,29.62 130.57,29.62
GND on BOTTOM (solid shape): 162.24,63.19 162.24,61.81 161.41,60.98 160.5,60.98 160.43,61.04 160.43,63.28 160.58,63.43 161.99,63.43
GND on BOTTOM (solid shape): 169.02,98.79 169.02,96.41 168.89,96.29 163.47,96.29 163.38,96.38 163.38,98.81 163.66,99.09 168.71,99.09
GND on BOTTOM (solid shape): 232.64,39.59 232.64,37.57 232.47,37.4 229.38,37.4 229.15,37.63 229.15,40.22 229.48,40.55 231.69,40.55
GND on BOTTOM (solid shape): 3.95,14.83 3.95,11.09 3.74,10.88 1.99,10.88 1.76,11.11 1.76,14.85 1.91,15.01 3.77,15.01
GND on BOTTOM (solid shape): 96.32,99.98 101.38,99.98 103.27,98.09 103.27,96.01 102.96,95.7 102.1,95.7 101.55,96.25 96.88,96.25 95.41,97.72 93.17,97.72 92.87,98.03 92.87,100.54 93.19,100.86 95.45,100.86
GND on BOTTOM (solid shape): 128.9,17.76 128.9,16.57 128.73,16.4 126.07,16.4 124.78,15.12 121.57,15.12 121.47,15.22 121.47,17.81 121.68,18.03 128.63,18.03
GND on BOTTOM (solid shape): 139.27,31.42 139.27,29.64 138.98,29.35 137.18,29.35 137.03,29.5 137.03,29.51 136.49,30.04 135.1,30.04 134.77,30.37 134.77,31.35 134.98,31.56 139.13,31.56
GND on BOTTOM (solid shape): 203.89,63.79 203.89,63.39 203.8,63.31 203.5,63.31 203.48,63.33 203.48,63.48 203.34,63.62 203.19,63.62 202.73,64.08 202.73,64.34 202.74,64.36 202.75,64.38 202.89,64.52 203.16,64.52
GND on BOTTOM (solid shape): 206.22,64.54 206.22,63.85 206.2,63.83 205.47,63.83 205.43,63.84 205.42,63.88 205.42,63.93 205.1,63.93 205.03,63.99 205.03,64.49 205.46,64.91 205.85,64.91
GND on BOTTOM (solid shape): 104.7,91.75 104.7,90.52 104.93,90.29 105.91,90.29 106.14,90.06 106.14,88.95 105.96,88.77 105.2,88.77 104.91,89.06 104.91,89.43 104.75,89.58 103.87,89.58 103.68,89.77 103.68,91.72 103.82,91.85 104.6,91.85
GND on BOTTOM (solid shape): 203.02,85.01 203.02,82.74 202.95,82.67 201.52,82.67 201.47,82.72 201.47,83.25 201.47,83.25 201.47,83.71 201.47,83.71 201.47,84.24 201.47,84.28 201.48,84.28 201.48,85.05 201.56,85.13 202.9,85.13
GND on BOTTOM (solid shape): 186.3,91.72 186.3,85.7 186.17,85.58 181.99,85.58 181.76,85.8 181.76,88.13 181.46,88.43 180.43,88.43 180.26,88.6 180.26,89.04 179.02,90.28 179.02,93.06 179.13,93.16 184.85,93.16
GND on BOTTOM (solid shape): 209.88,64.55 209.88,63.92 209.87,63.89 209.83,63.87 209.45,63.87 209.42,63.84 209.15,63.84 209.12,63.87 208.82,63.87 208.69,64 208.69,64.5 209.12,64.92 209.51,64.92
GND on BOTTOM (solid shape): 208.06,64.54 208.06,63.93 208.05,63.89 208.01,63.88 207.64,63.88 207.64,63.86 207.61,63.83 207.34,63.83 207.32,63.85 207.31,63.88 206.99,63.88 206.87,63.99 206.87,64.49 207.3,64.91 207.69,64.91
GND on BOTTOM (solid shape): 240.91,37.09 243.73,37.09 244.09,36.74 244.09,30.34 243.17,29.42 238.85,29.42 238.5,29.78 238.5,32.19 238.66,32.36 241.05,32.36 241.47,32.77 241.47,34.54 240.81,35.2 239.76,35.2 239.59,35.37 239.59,37.44 239.64,37.49 240.52,37.49
GND on BOTTOM (solid shape): 6.75,27.04 6.75,24.92 6.69,24.8 6.68,24.66 6.65,24.59 6.58,24.55 5.44,24.55 5.25,24.74 5.25,27.16 5.29,27.19 6.6,27.19
GND on BOTTOM (solid shape): 214.48,70.62 214.48,69.86 214.39,69.76 214.37,69.75 214.35,69.75 214.04,69.75 214.02,69.71 213.99,69.69 213.59,69.69 213.56,69.71 213.54,69.75 213.51,69.75 213.51,69.75 212.56,69.75 212.35,69.96 212.35,70.66 212.44,70.75 214.35,70.75
GND on BOTTOM (solid shape): 205.79,95.23 207.91,95.23 208.56,94.58 208.56,94.19 212.14,90.61 212.14,89.46 211.96,89.28 207.81,89.28 206.7,90.39 206.7,90.92 206.4,91.21 205.88,91.21 204.5,92.59 204.5,93.09 204.14,93.45 203.64,93.45 201.05,96.05 192.31,96.05 191.75,96.6 191.75,99.13 192.14,99.53 201.49,99.53
GND on BOTTOM (solid shape): 186.41,52.66 186.41,49.36 186.19,49.14 185.55,49.14 185.27,49.41 184.93,49.41 184.8,49.54 184.8,49.7 184.8,49.71 184.8,49.85 184.8,49.85 184.8,50.35 184.8,50.35 184.8,50.76 184.81,50.76 184.81,51.27 184.8,51.27 184.8,51.64 184.8,51.64 184.8,52.15 184.8,52.15 184.8,52.22 184.68,52.34 184.66,52.35 184.66,52.37 184.66,52.4 184.66,52.67 184.75,52.76 186.32,52.76
GND on BOTTOM (solid shape): 234.49,71.74 234.49,71.5 234.39,71.39 233.96,71.39 233.96,71.4 233.61,71.4 233.61,71.39 233.24,71.39 233.24,71.4 232.89,71.4 232.89,71.39 232.63,71.39 232.63,71.4 232.27,71.4 232.27,71.39 231.97,71.39 231.97,71.4 231.61,71.4 231.61,71.39 231.33,71.39 231.33,71.41 230.98,71.41 230.98,71.39 230.53,71.39 230.52,71.38 229.77,71.38 229.64,71.51 229.64,71.78 229.75,71.89 234.35,71.89
GND on BOTTOM (solid shape): 231.3,66.75 231.65,66.75 231.65,66.75 231.68,66.78 231.98,66.78 232.02,66.75 232.37,66.75 232.37,66.75 232.4,66.78 232.6,66.78 232.63,66.75 232.99,66.75 232.99,66.75 233.02,66.78 233.32,66.78 233.35,66.75 233.7,66.75 233.7,66.75 233.73,66.78 234.39,66.78 234.5,66.68 234.5,65.86 234.23,65.59 233.49,65.59 233.32,65.77 230.15,65.77 230.02,65.91 230.02,66.68 230.12,66.78 231.26,66.78
GND on BOTTOM (solid shape): 217.7,70.73 217.98,70.73 218,70.72 218.02,70.71 218.14,70.59 218.14,69.83 218.07,69.76 218.05,69.75 218.03,69.75 217.72,69.75 217.72,69.72 217.7,69.69 217.67,69.68 217.33,69.68 217.3,69.69 217.28,69.72 217.28,69.75 216.97,69.75 216.94,69.77 216.92,69.8 216.92,70.7 216.95,70.73 217.29,70.73 217.32,70.75 217.33,70.75 217.67,70.75
GND on BOTTOM (solid shape): 177.43,70.74 177.43,70.45 177.39,70.37 177.31,70.35 176.98,70.22 176.96,69.87 176.96,69.76 176.87,69.71 176.3,69.71 176.1,69.92 174.02,69.92 173.71,70.22 173.71,71 173.84,71.12 177.05,71.12
GND on BOTTOM (solid shape): 193.49,90.59 193.85,90.42 194.22,90.57 194.26,90.58 194.3,90.57 194.67,90.42 195.03,90.59 195.36,90.59 195.44,90.52 195.44,88.05 195.31,87.93 192.76,87.93 192.58,88.1 192.58,88.87 192.25,89.21 192.25,90.36 192.48,90.59
GND on BOTTOM (solid shape): 215.85,70.79 215.89,70.78 215.9,70.74 215.9,70.73 216.23,70.73 216.25,70.73 216.26,70.72 216.32,70.66 216.32,69.81 216.28,69.76 216.26,69.75 216.24,69.75 215.93,69.75 215.93,69.73 215.92,69.69 215.88,69.68 215.53,69.68 215.49,69.69 215.47,69.72 215.47,69.75 215.14,69.75 215.1,69.78 215.1,70.68 215.12,70.72 215.15,70.73 215.5,70.73 215.5,70.76 215.53,70.79
GND on BOTTOM (solid shape): 178,21.79 178,20.53 177.9,20.43 176.59,20.43 176.58,20.44 175.95,19.81 174.63,19.81 174.61,19.83 173.78,19.83 173.49,20.12 173.49,20.64 175.04,20.64 175.04,20.59 175.05,20.54 175.06,20.49 175.09,20.44 175.12,20.4 175.15,20.37 175.19,20.34 175.24,20.31 175.29,20.3 175.34,20.29 175.39,20.29 175.44,20.3 175.49,20.31 175.54,20.34 175.58,20.37 175.61,20.4 175.64,20.44 175.67,20.49 175.68,20.54 175.69,20.59 175.69,20.64 175.68,20.69 175.67,20.74 175.64,20.79 175.61,20.83 175.58,20.87 175.54,20.9 175.49,20.92 175.44,20.94 175.39,20.94 175.34,20.94 175.29,20.94 175.24,20.92 175.19,20.9 175.15,20.87 175.12,20.83 175.09,20.79 175.06,20.74 175.05,20.69 175.04,20.64 173.49,20.64 173.49,21.82 173.55,21.88 177.91,21.88
GND on BOTTOM (solid shape): 170.87,92.06 170.87,84.21 170.74,84.08 168.64,84.08 168.45,84.27 168.45,90.41 168.5,90.5 168.6,90.49 169.19,90.81 168.6,91.13 168.5,91.12 168.45,91.21 168.45,91.89 168.72,92.17 170.76,92.17
GND on BOTTOM (solid shape): 227.22,90.41 227.22,89.21 227.2,89.17 227.17,89.16 227.12,89.16 227.12,88.39 227.17,88.39 227.2,88.38 227.22,88.34 227.22,87.88 227.2,87.84 227.17,87.83 227.13,87.83 227.13,87.07 227.16,87.05 227.17,87.03 227.17,87.01 227.16,86.98 227.13,86.96 224.87,86.96 224.79,87.03 224.78,87.05 224.78,87.07 224.78,87.86 224.76,87.87 224.76,88.32 224.78,88.36 224.82,88.37 224.82,89.14 224.81,89.14 224.78,89.15 224.76,89.19 224.76,89.59 224.78,89.62 224.81,89.64 224.82,89.64 224.82,90.4 224.8,90.43 224.8,90.46 224.82,90.49 224.86,90.54 227.09,90.54
GND on BOTTOM (solid shape): outline of 94 points within 72.56,55.02 77.77,57.44
GND on BOTTOM (solid shape): outline of 93 points within 33.58,84.46 38.52,93.06
GND on BOTTOM (solid shape): outline of 266 points within 213.4,41.94 222.64,53.25
GND on BOTTOM (solid shape): outline of 1103 points within 0.3,7.01 252.89,105.19
GND on LAY2 (solid shape): outline of 65066 points within 0.41,7.01 252.89,105.19
GND on LAY3 (solid shape): outline of 1066 points within 100.26,10.93 160.19,28.28
GND on LAY3 (solid shape): outline of 2477 points within 0.41,7.01 252.89,105.19
GND on LAY4 (solid shape): outline of 43912 points within 0.41,7.01 252.89,105.19
GND on LAY5 (solid shape): outline of 66837 points within 0.41,7.01 252.89,105.19
GND on LAY6 (solid shape): outline of 1393 points within 0.41,7.01 252.89,105.19
GND on LAY7 (solid shape): 12.67,17.03 11.99,17.03 11.99,20.85 12.67,20.85
GND on LAY7 (solid shape): outline of 64675 points within 0.41,7.01 252.89,105.19
GND_EARTH on TOP (solid shape): 82.76,23.1 82.76,17.61 82.61,17.46 80.28,17.46 80.13,17.61 80.13,19.56 80.13,19.56 80.13,23.16 80.28,23.32 82.54,23.32
GND_EARTH on LAY2 (solid shape): outline of 772 points within 80.14,10.94 108.51,42.71
GND_EARTH on LAY3 (solid shape): outline of 772 points within 80.14,10.94 108.53,42.71
GND_EARTH on LAY4 (solid shape): outline of 860 points within 80.14,10.94 108.53,42.71
GND_EARTH on LAY5 (solid shape): outline of 772 points within 80.14,10.94 108.53,42.71
GND_EARTH on LAY6 (solid shape): outline of 772 points within 80.14,10.94 108.53,42.71
GND_EARTH on LAY7 (solid shape): outline of 772 points within 80.14,10.94 108.53,42.71
V1P0_LL on TOP (solid shape): 165.44,59.47 165.44,54.93 165.01,54.5 161.62,54.5 161.36,54.75 161.36,56.63 160.71,57.29 160.71,57.29 160.57,57.43 160.57,59.36 160.88,59.66 165.25,59.66
VCC1_USB3.0 on BOTTOM (solid shape): 13.62,92.98 13.62,92.13 13.62,92.12 13.62,90.05 15.67,88 19.1,88 20.27,86.83 21.46,86.83 21.63,86.65 21.63,84.95 21.3,84.62 20.38,84.62 19.31,85.68 13.48,85.68 11.05,88.11 11.05,91.2 11.2,91.5 11.05,91.8 11.05,92.93 11.36,93.24 13.36,93.24
VCC2_USB3.0 on BOTTOM (solid shape): 40.32,92.23 40.32,90.76 42.05,89.03 48.52,89.03 48.76,88.79 48.76,87.05 48.76,87.05 48.76,85.71 47.94,84.88 39.46,84.88 39.02,85.33 39.02,87.08 38.07,88.03 38.07,89.54 38.2,89.82 38.08,90.11 38.07,90.12 38.07,90.14 37.53,90.67 37.53,92.32 37.77,92.55 40,92.55
VCC_USB2 on TOP (solid shape): 45.36,18.17 48.87,18.17 48.92,18.16 48.97,18.17 52.81,18.17 53.47,17.5 53.47,16.64 53.18,16.35 51.88,16.35 51.39,16.84 43.54,16.84 42.32,18.07 42.32,19.61 42.44,19.74 43.79,19.74
VCC_USB3 on TOP (solid shape): 68.96,17.94 68.96,16.63 68.58,16.25 67.85,16.25 66.46,14.86 63.18,14.86 62.9,15.14 60.95,15.14 60.88,15.21 60.88,16.98 61.11,17.22 66.22,17.22 67.16,18.16 68.74,18.16
VCCRTCEXT on BOTTOM (solid shape): 192.38,54.38 192.38,52.82 192.38,52.82 192.38,52.35 192.26,52.23 190.9,52.23 190.71,52.42 190.71,54.17 191,54.45 192.31,54.45
VDD12 on BOTTOM (solid shape): 146.82,76.22 146.82,74.86 146.72,74.75 142.21,74.75 142.11,74.86 142.11,76.22 142.19,76.3 146.75,76.3
VDDIO_8625 on TOP (solid shape): outline of 357 points within 135.83,77.38 141.71,89.67
VIN_LCD on BOTTOM (solid shape): 121.07,95.16 121.07,90.79 120.99,90.79 120.19,89.99 120.19,85.8 119.64,85.25 117.28,85.25 116.9,85.63 116.9,95.8 117.12,96.03 120.2,96.03
+V_ADP_IN on BOTTOM (solid shape): 142.56,22.84 142.56,18.5 142.39,18.32 133.85,18.32 133.4,18.77 133.38,18.81 133.36,18.85 133.47,19.14 133.32,19.41 133.32,22.73 133.65,23.06 142.35,23.06
+V_LED on BOTTOM (solid shape): 104.62,97.26 104.62,96.01 104.84,95.78 106.25,95.78 106.63,95.4 106.63,92.88 105.97,92.22 97.38,92.22 97.36,92.24 94.76,92.24 94.44,91.92 94.44,90.47 94.46,90.46 94.46,90.24 94.33,90.11 92.88,90.11 92.8,90.19 92.8,92.43 92.42,92.81 92.42,96.1 93.48,97.15 95.26,97.15 96.55,95.86 101.47,95.86 101.87,95.45 103.21,95.45 103.64,95.88 103.64,97.35 103.7,97.42 104.46,97.42
+VSYS_DCIN on TOP (solid shape): 212.53,103.72 212.53,102.5 212.41,102.38 210.75,102.38 210.53,102.17 210.53,100.47 208.97,98.9 208.94,98.91 208.64,98.88 208.45,98.64 208.45,98.63 207.8,97.98 204.08,97.98 203.99,98.07 203.99,99.78 204.34,100.12 207.05,100.12 208.68,101.75 208.68,103.44 209.17,103.93 212.31,103.93
+VSYS_DCIN on TOP (solid shape): outline of 970 points within 12.13,48.32 170.73,102.36
+VSYS_DCIN on BOTTOM (solid shape): 119.53,83.65 119.53,79.82 119.16,79.45 117.23,79.45 116.57,80.11 116.57,83.46 116.93,83.83 119.35,83.83
+VSYS_DCIN on BOTTOM (solid shape): outline of 691 points within 141.58,19.39 237.89,104.46
+VSYS_DCIN on LAY3 (solid shape): outline of 234 points within 166.62,98.76 207.08,104.14
CORE_PHASE on TOP (solid shape): 194.87,101.7 194.87,97.18 192.96,95.26 190.1,95.26 189.71,95.65 189.71,96.44 188.83,97.31 183.3,97.31 183.29,97.3 182.28,97.3 182.07,97.51 182.07,100.78 182.56,101.27 183.65,101.27 183.89,101.51 183.89,102.23 184.21,102.55 194.02,102.55
EVDD10 on BOTTOM (solid shape): 128.43,31.78 128.75,31.78 128.77,31.76 129.5,31.49 130.23,31.76 130.25,31.78 130.52,31.78 130.66,31.91 133.91,31.91 133.96,31.86 133.96,30.12 133.75,29.9 126.78,29.9 126.5,30.18 126.5,31.56 126.48,31.57 126.48,31.87 126.6,31.99 128.22,31.99
EVDD10 on LAY3 (solid shape): 130.7,47.53 130.7,46.9 130.32,46.52 127.06,46.52 123.37,42.83 123.37,39.24 124.34,38.27 127.11,38.27 128.12,37.26 128.12,33.66 128.12,33.65 128.08,33.47 128.12,33.3 128.12,33.29 128.12,31.5 127.65,31.03 126.6,31.03 126.36,31.28 126.36,31.83 126.8,32.28 126.8,36.34 126.27,36.88 122.6,36.88 121.85,37.63 121.85,43.89 125.95,47.99 130.24,47.99
FAN_VCC on TOP (solid shape): 165.42,22.28 165.42,17.48 165.3,17.36 163.8,17.36 163.72,17.43 163.72,22.26 163.95,22.49 165.22,22.49
GT_PHASE on TOP (solid shape): 228.95,101.58 228.95,96.13 227.28,94.47 223.44,94.47 222.41,95.51 216.46,95.51 215.88,96.08 215.88,98.8 216.12,99.04 217.2,99.04 217.58,99.42 217.58,100.17 217.67,100.4 217.6,100.63 217.58,100.66 218.92,102 228.53,102
LCD_VCC on BOTTOM (solid shape): 133.23,97.35 133.23,94.38 127.67,88.82 127.67,85.44 127.45,85.23 125.7,85.23 125.51,85.42 125.51,90.62 130.54,95.65 130.54,97.42 130.73,97.61 132.97,97.61
OVPA on BOTTOM (solid shape): 107.49,97.33 107.49,96.41 107.31,96.24 105.16,96.24 105.02,96.38 105.02,97.39 105.11,97.48 107.33,97.48
REGOUT on BOTTOM (solid shape): 130,38.06 130,37.37 133.35,34.02 133.86,34.02 134.04,33.84 134.04,32.52 133.95,32.43 130.71,32.43 130.65,32.49 130.65,34.31 128.35,36.61 128.35,38.35 128.39,38.4 129.66,38.4
SA_PHASE on TOP (solid shape): 167.45,93.72 167.45,88.97 167.09,88.6 161.22,88.6 160.79,89.04 160.79,91.68 160.85,91.74 162.37,91.74 162.97,92.34 162.97,93.56 163.33,93.91 167.26,93.91
SW1 on TOP (solid shape): 23.61,79.26 23.61,73.99 23.2,73.57 17.9,73.57 17.3,74.16 17.3,75.63 17.36,75.83 17.3,76.02 17.3,79.68 17.54,79.92 22.95,79.92
SW2 on TOP (solid shape): 12.95,77.74 12.95,72.25 12.64,71.94 6.61,71.94 6.26,72.29 6.26,77.7 6.71,78.15 12.54,78.15
N34559149 on BOTTOM (solid shape): 128.07,84.13 128.07,81.91 128.15,81.83 128.15,81.7 128.14,81.62 128.15,81.53 128.15,80.44 128.05,80.34 127.09,80.34 126.41,79.65 124.3,79.65 124.11,79.84 124.11,81.26 124.26,81.42 125.15,81.42 125.48,81.75 125.48,84.15 125.79,84.45 127.75,84.45
N35255522 on TOP (solid shape): 149.14,57.92 149.14,53.74 147.25,51.85 143.97,51.85 143.85,51.98 143.85,54.36 144,54.52 146.72,54.52 147.03,54.83 147.03,58.16 147.15,58.28 148.79,58.28
N35256155 on BOTTOM (solid shape): 154.72,48.31 154.72,47.53 154.64,47.46 154.64,45.17 153.85,44.38 152.66,44.38 152.53,44.51 152.53,47.9 153.08,48.45 154.58,48.45
N35256211 on BOTTOM (solid shape): 156.89,53.42 156.89,51.91 156.75,51.77 155.28,51.77 154.69,51.19 154.69,50.44 154.63,50.38 153.97,50.38 153.9,50.44 153.9,51.27 153.4,51.77 152.33,51.77 152.14,51.96 152.14,53.48 152.24,53.58 156.74,53.58
N36034869 on TOP (solid shape): 161.5,86.67 161.5,84.63 161.93,84.2 161.93,83.55 161.3,82.91 157.46,82.91 157.03,83.35 157.03,86.48 157.37,86.83 161.35,86.83
N36034873 on TOP (solid shape): 215.04,102.8 215.04,95.44 214.88,95.27 210.83,95.27 210.65,95.45 210.58,95.54 210.5,95.6 210.4,95.7 210.4,99.87 210.75,100.22 210.75,102.01 210.88,102.14 212.48,102.14 212.96,102.62 213.57,102.62 213.99,103.04 214.8,103.04
N36034873 on BOTTOM (solid shape): 215.5,102.76 215.5,99.86 214.48,98.84 209.12,98.84 208.88,99.08 208.88,102.85 209.12,103.09 215.17,103.09
N36035212 on TOP (solid shape): 181.45,102.41 181.45,102.4 181.52,102.25 181.65,102.14 181.65,97.8 181.54,97.68 176.95,97.68 176.71,97.77 176.47,97.68 175.06,97.68 174.64,97.26 171.37,97.26 171.16,97.47 171.16,101.57 171.35,101.76 176.61,101.76 177.39,102.54 181.32,102.54
N36035212 on BOTTOM (solid shape): 175.34,98.9 175.34,97.28 174.31,96.25 169.61,96.25 169.55,96.31 169.55,98.92 169.7,99.07 175.18,99.07
N36971603 on BOTTOM (solid shape): 181.8,29.12 181.8,24.71 180.79,23.71 171.48,23.71 171.14,24.05 171.14,25.98 171.44,26.28 178.85,26.28 179.13,26.55 179.13,29.12 179.32,29.31 181.6,29.31
N37063122 on TOP (solid shape): outline of 691 points within 234.23,32.47 250.18,42.49
N37063122 on BOTTOM (solid shape): 239.39,38.04 239.39,35.3 239.73,34.96 240.64,34.96 241.08,34.53 241.08,32.89 240.81,32.62 238.41,32.62 238.05,32.98 238.05,35.21 237.98,35.29 237.98,38.07 238.08,38.17 239.26,38.17
N37412835 on BOTTOM (solid shape): 145.14,79.25 145.14,79.2 145.2,79.2 145.96,78.43 146.71,78.43 146.82,78.32 146.82,76.96 146.68,76.82 143.49,76.82 143.36,76.95 143.36,79.34 143.36,79.47 142.43,80.4 142.43,81.1 142.5,81.15 142.55,81.21 143.19,81.21
N37456959 on BOTTOM (solid shape): 113.77,95.32 113.77,92.11 112.93,91.27 112.93,83.84 112.68,83.59 107.49,83.59 107.29,83.78 107.29,95.56 107.54,95.8 113.29,95.8
N37767608 on TOP (solid shape): 118.72,27.5 118.72,26.09 119.47,25.34 119.47,23.6 118.88,23.01 115.56,23.01 115.14,23.43 115.14,25.55 115.92,26.32 115.92,27.63 116.41,28.12 118.11,28.12
N37767608 on BOTTOM (solid shape): outline of 339 points within 115.21,18.72 127.72,26.84
N37767652 on TOP (solid shape): 115.52,28.19 115.52,26.77 115.47,26.71 112.73,26.71 112.62,26.82 112.62,28.14 112.78,28.31 115.41,28.31
N37767697 on BOTTOM (solid shape): 132.64,23.6 132.64,22.39 132.52,22.11 132.64,21.83 132.64,18.94 132.31,18.61 128.67,18.61 128.52,18.77 128.52,23.48 128.78,23.74 132.5,23.74
N37928976 on BOTTOM (solid shape): 106.74,91.68 106.74,90.67 106.65,90.58 105.01,90.58 104.91,90.69 104.91,91.61 105.09,91.79 106.62,91.79

Small or netless copper shapes (teardrops, artwork), in the pictures only: 2 on TOP

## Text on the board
Ref Des/Silkscreen Bottom: V1.03 | BOT | 5000-0006-2103 | 2016.0617.1700 | BOTTOM | UM7L_MAIN_PCB | REF | BD | BA | BB | BC | BE | BF
Ref Des/Silkscreen Top: 5000-0006-2103 | 2016.0617.1700 | TOP | V1.03 | REF | UM7L_MAIN_PCB | TD | TG | TC | TE | TF
User.22: FIGURE | SIZE | 9.84 | 15.75 | 27.56 | 31.5 | 37.4 | 62.99 | 90.55 | 98.43 | 133.86 | 149.61 | 39.37 | 43.0 | 43.31 | 51.18 | 55.12 | 59.06 | 63.0 | 78.74 | 125.98 | 59.06x23.62 | 94.49x23.62 | 98.43x35.43 | 102.36x39.37 | DRILL CHART: TOP to BOTTOM | ALL UNITS ARE IN MILS | TOLERANCE | +0.0/-0.0 | +2.0/-2.0 | PLATED | NON-PLATED | QTY | 2702 | 872 | 10 | 4 | 8 | 2 | 6 | 3 | 1
